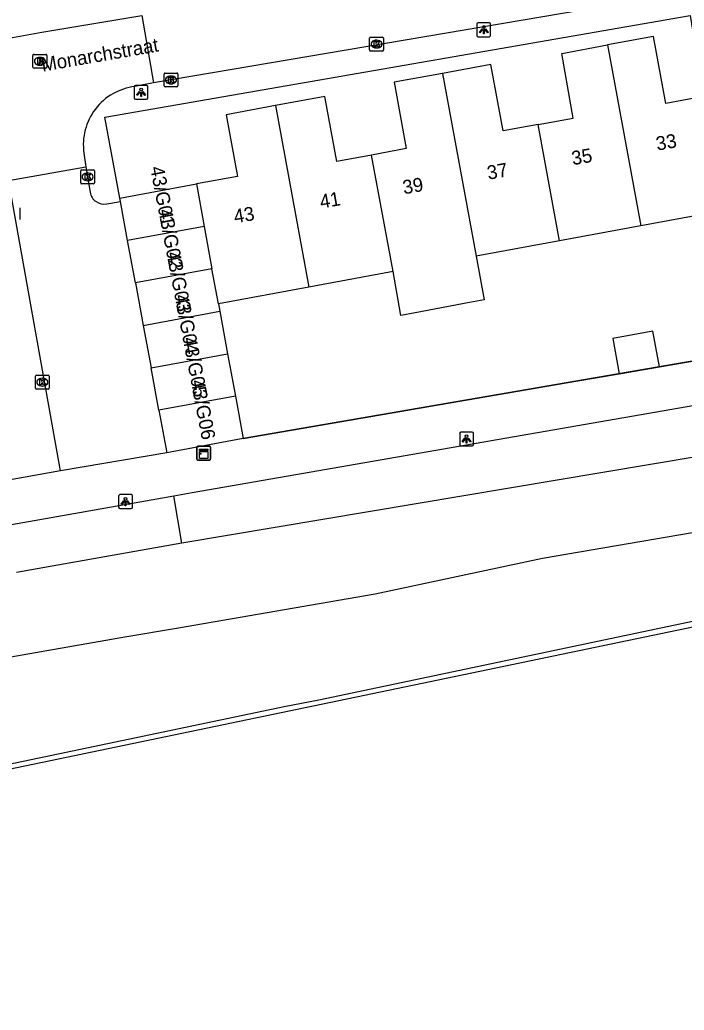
# Model space of a CAD drawing. Extents: x 162880 to 165536, y 384011 to 385179.
# Drawn here: x 164359.8 to 164407.7, y 384233.6 to 384305 of the extents above; entities that cross this region are included whole.
import ezdxf

# ---------------------------------------------------------------- set-up
doc = ezdxf.new("R2010")
doc.units = 0
for name, color, linetype in [('IMGEO_Geluidsscherm', 7, 'Continuous'), ('IMGEO_Groenvoorziening', 7, 'Continuous'), ('IMGEO_Hek', 7, 'Continuous'), ('IMGEO_Kast', 7, 'Continuous'), ('IMGEO_Kolk', 7, 'Continuous'), ('IMGEO_Lichtpunt', 7, 'Continuous'), ('IMGEO_Muur', 7, 'Continuous'), ('IMGEO_Openbare_ruimte_label', 7, 'Continuous'), ('IMGEO_Pand', 7, 'Continuous'), ('IMGEO_Pand_nummerreeks', 7, 'Continuous'), ('IMGEO_Rijbaan_lokaal_open', 7, 'Continuous'), ('IMGEO_Rioolput', 7, 'Continuous'), ('IMGEO_Spoorbaan_halfverhard', 7, 'Continuous'), ('IMGEO_Voetpad_open', 7, 'Continuous')]:
    doc.layers.add(name, color=color, linetype=linetype)

msp = doc.modelspace()

# ---------------------------------------------------------------- linework, layer by layer
at = {"layer": 'IMGEO_Geluidsscherm'}
msp.add_lwpolyline([(164676.85, 384317.503), (164663.933, 384314.802), (164648.266, 384311.595), (164636.969, 384309.223), (164597.183, 384300.976), (164565.574, 384294.368), (164548.747, 384290.97), (164534.634, 384287.879), (164524.441, 384285.774), (164509.439, 384282.631), (164506.722, 384282.083), (164492.433, 384279.293), (164482.587, 384277.14), (164470.079, 384274.477), (164466.147, 384273.624), (164450.636, 384270.401), (164434.466, 384267.046), (164426.586, 384265.503), (164423.587, 384264.967), (164410.248, 384262.029), (164381.356, 384255.946), (164378.846, 384255.471), (164286.152, 384236.059)], dxfattribs=at)
at = {"layer": 'IMGEO_Groenvoorziening'}
for points in [[(164332.753, 384254.442), (164367.352, 384260.503), (164371.077, 384261.125), (164385.399, 384263.612), (164397.49, 384266.196), (164412.669, 384268.778), (164431.26, 384272.662), (164431.272, 384272.664), (164433.193, 384273.044), (164448.321, 384276.269), (164450.983, 384279.512), (164456.803, 384278.493), (164479.257, 384283.495), (164483.175, 384284.701), (164485.578, 384284.269), (164503.501, 384287.513), (164502.968, 384290.256)], [(164408.706, 384273.531), (164371.45, 384267.278)], [(164371.45, 384267.278), (164370.883, 384270.681)], [(164371.45, 384267.278), (164359.532, 384265.161)]]:
    msp.add_lwpolyline(points, dxfattribs=at)
at = {"layer": 'IMGEO_Hek'}
msp.add_lwpolyline([(164444.165, 384268.675), (164308.907, 384240.511), (164298.742, 384238.478), (164283.523, 384235.158)], dxfattribs=at)
at = {"layer": 'IMGEO_Kast'}
for p, q in [((164372.535, 384273.339), (164372.535, 384274.18)), ((164372.535, 384274.18), (164372.535, 384273.339)), ((164372.61, 384274.264), (164373.451, 384274.264)), ((164373.451, 384274.264), (164372.61, 384274.264)), ((164373.535, 384274.189), (164373.535, 384273.348)), ((164373.535, 384273.348), (164373.535, 384274.189)), ((164373.46, 384273.264), (164372.619, 384273.264)), ((164372.619, 384273.264), (164373.46, 384273.264))]:
    msp.add_line(p, q, dxfattribs=at)
for points in [[(164372.73, 384274.054), (164373.33, 384274.054), (164373.33, 384273.969), (164372.73, 384273.969), (164372.73, 384274.054)], [(164372.73, 384273.879), (164373.33, 384273.879), (164373.33, 384273.39), (164372.73, 384273.39), (164372.73, 384273.879)]]:
    msp.add_lwpolyline(points, dxfattribs=at)
msp.add_circle((164372.814, 384273.728), 0.0377, dxfattribs=at)
for centre, start, end in [((164372.613, 384274.186), 92.4484, 184.28452), ((164372.613, 384274.186), 92.4484, 184.28452), ((164373.457, 384274.186), 2.4484, 94.28452), ((164373.457, 384274.186), 2.4484, 94.28452), ((164372.613, 384273.342), 182.4484, 274.28452), ((164372.613, 384273.342), 182.4484, 274.28452), ((164373.457, 384273.342), 272.4484, 4.28452), ((164373.457, 384273.342), 272.4484, 4.28452)]:
    msp.add_arc(centre, 0.0779, start, end, dxfattribs=at)
at = {"layer": 'IMGEO_Kolk'}
for p, q in [((164385.012, 384302.86), (164385.012, 384303.712)), ((164385.087, 384303.786), (164385.939, 384303.786)), ((164385.5, 384303.566), (164385.525, 384303.566)), ((164386.013, 384303.712), (164386.013, 384302.86)), ((164385.939, 384302.786), (164385.087, 384302.786)), ((164385.523, 384303.006), (164385.498, 384303.006)), ((164370.175, 384300.272), (164370.175, 384301.124)), ((164370.25, 384301.198), (164371.102, 384301.198)), ((164370.663, 384300.978), (164370.688, 384300.978)), ((164371.176, 384301.124), (164371.176, 384300.272)), ((164371.102, 384300.198), (164370.25, 384300.198)), ((164370.686, 384300.418), (164370.661, 384300.418)), ((164364.16, 384293.283), (164364.16, 384294.135)), ((164364.235, 384294.209), (164365.087, 384294.209)), ((164365.161, 384294.135), (164365.161, 384293.283)), ((164364.671, 384293.429), (164364.646, 384293.429)), ((164364.648, 384293.989), (164364.673, 384293.989)), ((164365.087, 384293.209), (164364.235, 384293.209)), ((164359.768, 384291.469), (164359.768, 384290.617)), ((164360.895, 384278.465), (164360.895, 384279.317)), ((164360.97, 384279.391), (164361.822, 384279.391)), ((164361.383, 384279.171), (164361.408, 384279.171)), ((164361.896, 384279.317), (164361.896, 384278.465)), ((164361.822, 384278.391), (164360.97, 384278.391)), ((164361.406, 384278.611), (164361.381, 384278.611))]:
    msp.add_line(p, q, dxfattribs=at)
for points in [[(164385.012, 384302.86), (164385.012, 384303.712)], [(164385.087, 384303.786), (164385.939, 384303.786)], [(164385.333, 384303.486), (164385.456, 384303.486), (164385.456, 384303.335), (164385.586, 384303.486), (164385.75, 384303.486), (164385.604, 384303.335), (164385.757, 384303.086), (164385.605, 384303.086), (164385.52, 384303.25), (164385.456, 384303.183), (164385.456, 384303.086), (164385.333, 384303.086), (164385.333, 384303.486)], [(164386.013, 384303.712), (164386.013, 384302.86)], [(164385.939, 384302.786), (164385.087, 384302.786)], [(164370.175, 384300.272), (164370.175, 384301.124)], [(164370.25, 384301.198), (164371.102, 384301.198)], [(164370.496, 384300.898), (164370.619, 384300.898), (164370.619, 384300.747), (164370.749, 384300.898), (164370.913, 384300.898), (164370.767, 384300.747), (164370.92, 384300.498), (164370.768, 384300.498), (164370.683, 384300.662), (164370.619, 384300.595), (164370.619, 384300.498), (164370.496, 384300.498), (164370.496, 384300.898)], [(164371.176, 384301.124), (164371.176, 384300.272)], [(164371.102, 384300.198), (164370.25, 384300.198)], [(164364.16, 384293.283), (164364.16, 384294.135)], [(164364.235, 384294.209), (164365.087, 384294.209)], [(164365.161, 384294.135), (164365.161, 384293.283)], [(164364.481, 384293.909), (164364.604, 384293.909), (164364.604, 384293.758), (164364.734, 384293.909), (164364.898, 384293.909), (164364.752, 384293.758), (164364.905, 384293.509), (164364.753, 384293.509), (164364.668, 384293.673), (164364.604, 384293.606), (164364.604, 384293.509), (164364.481, 384293.509), (164364.481, 384293.909)], [(164365.087, 384293.209), (164364.235, 384293.209)], [(164359.768, 384291.469), (164359.768, 384290.617)], [(164360.895, 384278.465), (164360.895, 384279.317)], [(164360.97, 384279.391), (164361.822, 384279.391)], [(164361.216, 384279.091), (164361.339, 384279.091), (164361.339, 384278.94), (164361.469, 384279.091), (164361.633, 384279.091), (164361.487, 384278.94), (164361.64, 384278.691), (164361.488, 384278.691), (164361.403, 384278.855), (164361.339, 384278.788), (164361.339, 384278.691), (164361.216, 384278.691), (164361.216, 384279.091)], [(164361.896, 384279.317), (164361.896, 384278.465)], [(164361.822, 384278.391), (164360.97, 384278.391)]]:
    msp.add_lwpolyline(points, dxfattribs=at)
for centre, start, end in [((164385.089, 384303.71), 91.55205, 178.44795), ((164385.089, 384303.71), 91.55205, 178.44795), ((164385.937, 384303.71), 1.55205, 88.44795), ((164385.937, 384303.71), 1.55205, 88.44795), ((164385.089, 384302.862), 181.55205, 268.44795), ((164385.089, 384302.862), 181.55205, 268.44795), ((164385.937, 384302.862), 271.55205, 358.44795), ((164385.937, 384302.862), 271.55205, 358.44795), ((164370.252, 384301.122), 91.55205, 178.44795), ((164370.252, 384301.122), 91.55205, 178.44795), ((164371.1, 384301.122), 1.55205, 88.44795), ((164371.1, 384301.122), 1.55205, 88.44795), ((164370.252, 384300.274), 181.55205, 268.44795), ((164370.252, 384300.274), 181.55205, 268.44795), ((164371.1, 384300.274), 271.55205, 358.44795), ((164371.1, 384300.274), 271.55205, 358.44795), ((164364.237, 384294.133), 91.55205, 178.44795), ((164364.237, 384294.133), 91.55205, 178.44795), ((164365.085, 384294.133), 1.55205, 88.44795), ((164365.085, 384294.133), 1.55205, 88.44795), ((164364.237, 384293.285), 181.55205, 268.44795), ((164364.237, 384293.285), 181.55205, 268.44795), ((164365.085, 384293.285), 271.55205, 358.44795), ((164365.085, 384293.285), 271.55205, 358.44795), ((164360.972, 384279.315), 91.55205, 178.44795), ((164360.972, 384279.315), 91.55205, 178.44795), ((164361.82, 384279.315), 1.55205, 88.44795), ((164361.82, 384279.315), 1.55205, 88.44795), ((164360.972, 384278.467), 181.55205, 268.44795), ((164360.972, 384278.467), 181.55205, 268.44795), ((164361.82, 384278.467), 271.55205, 358.44795), ((164361.82, 384278.467), 271.55205, 358.44795)]:
    msp.add_arc(centre, 0.0765, start, end, dxfattribs=at)
for centre, major_axis, ratio, start_param, end_param in [((164385.499, 384303.286), (-0.387, 0.002), 0.722429, 4.712389, 7.853982), ((164385.524, 384303.286), (-0.39, 0.002), 0.717154, 1.570796, 4.712389), ((164370.662, 384300.698), (-0.387, 0.002), 0.722429, 4.712389, 7.853982), ((164370.687, 384300.698), (-0.39, 0.002), 0.717154, 1.570796, 4.712389), ((164364.647, 384293.709), (-0.387, 0.002), 0.722429, 4.712389, 7.853982), ((164364.672, 384293.709), (-0.39, 0.002), 0.717154, 1.570796, 4.712389), ((164361.382, 384278.891), (-0.387, 0.002), 0.722429, 4.712389, 7.853982), ((164361.407, 384278.891), (-0.39, 0.002), 0.717154, 1.570796, 4.712389)]:
    msp.add_ellipse(centre, major_axis=major_axis, ratio=ratio, start_param=start_param, end_param=end_param, dxfattribs=at)
at = {"layer": 'IMGEO_Lichtpunt'}
for p, q in [((164393.649, 384304.816), (164392.841, 384304.816)), ((164393.649, 384304.816), (164392.841, 384304.816)), ((164392.747, 384304.721), (164392.747, 384303.914)), ((164392.747, 384304.721), (164392.747, 384303.914)), ((164393.743, 384303.914), (164393.743, 384304.721)), ((164393.743, 384303.914), (164393.743, 384304.721)), ((164392.841, 384303.82), (164393.649, 384303.82)), ((164392.841, 384303.82), (164393.649, 384303.82)), ((164368.019, 384300.211), (164368.019, 384299.404)), ((164368.019, 384300.211), (164368.019, 384299.404)), ((164368.921, 384300.306), (164368.113, 384300.306)), ((164368.921, 384300.306), (164368.113, 384300.306)), ((164369.015, 384299.404), (164369.015, 384300.211)), ((164369.015, 384299.404), (164369.015, 384300.211)), ((164368.113, 384299.31), (164368.921, 384299.31)), ((164368.113, 384299.31), (164368.921, 384299.31)), ((164391.507, 384275.196), (164391.507, 384274.389)), ((164391.507, 384275.196), (164391.507, 384274.389)), ((164392.409, 384275.291), (164391.601, 384275.291)), ((164392.409, 384275.291), (164391.601, 384275.291)), ((164392.503, 384274.389), (164392.503, 384275.196)), ((164392.503, 384274.389), (164392.503, 384275.196)), ((164391.601, 384274.295), (164392.409, 384274.295)), ((164391.601, 384274.295), (164392.409, 384274.295)), ((164366.901, 384270.679), (164366.901, 384269.872)), ((164366.901, 384270.679), (164366.901, 384269.872)), ((164367.803, 384270.774), (164366.995, 384270.774)), ((164367.803, 384270.774), (164366.995, 384270.774)), ((164367.897, 384269.872), (164367.897, 384270.679)), ((164367.897, 384269.872), (164367.897, 384270.679)), ((164366.995, 384269.778), (164367.803, 384269.778)), ((164366.995, 384269.778), (164367.803, 384269.778))]:
    msp.add_line(p, q, dxfattribs=at)
for points in [[(164393.121, 384304.385), (164393.16, 384304.357), (164392.972, 384304.095), (164392.934, 384304.122), (164393.121, 384304.385)], [(164393.223, 384304.337), (164393.27, 384304.337), (164393.27, 384304.015), (164393.223, 384304.015), (164393.223, 384304.337)], [(164393.333, 384304.357), (164393.371, 384304.384), (164393.558, 384304.122), (164393.519, 384304.094), (164393.333, 384304.357)], [(164368.393, 384299.875), (164368.432, 384299.847), (164368.244, 384299.585), (164368.206, 384299.612), (164368.393, 384299.875)], [(164368.495, 384299.827), (164368.542, 384299.827), (164368.542, 384299.505), (164368.495, 384299.505), (164368.495, 384299.827)], [(164368.605, 384299.847), (164368.643, 384299.874), (164368.83, 384299.612), (164368.791, 384299.584), (164368.605, 384299.847)], [(164391.881, 384274.86), (164391.92, 384274.832), (164391.732, 384274.57), (164391.694, 384274.597), (164391.881, 384274.86)], [(164391.983, 384274.812), (164392.03, 384274.812), (164392.03, 384274.49), (164391.983, 384274.49), (164391.983, 384274.812)], [(164392.093, 384274.832), (164392.131, 384274.859), (164392.318, 384274.597), (164392.279, 384274.569), (164392.093, 384274.832)], [(164367.275, 384270.343), (164367.314, 384270.315), (164367.126, 384270.053), (164367.088, 384270.08), (164367.275, 384270.343)], [(164367.377, 384270.295), (164367.424, 384270.295), (164367.424, 384269.973), (164367.377, 384269.973), (164367.377, 384270.295)], [(164367.487, 384270.315), (164367.525, 384270.342), (164367.712, 384270.08), (164367.673, 384270.052), (164367.487, 384270.315)]]:
    msp.add_lwpolyline(points, dxfattribs=at)
for centre in [(164393.246, 384304.519), (164368.518, 384300.009), (164392.006, 384274.994), (164367.4, 384270.477)]:
    msp.add_circle(centre, 0.0994, dxfattribs=at)
for centre, start, end in [((164392.841, 384304.721), 90, 180), ((164392.841, 384304.721), 90, 180), ((164393.649, 384304.721), 0, 90), ((164393.649, 384304.721), 0, 90), ((164392.841, 384303.914), 180, 270), ((164392.841, 384303.914), 180, 270), ((164393.649, 384303.914), 270, 0), ((164393.649, 384303.914), 270, 360), ((164368.113, 384300.211), 90, 180), ((164368.113, 384300.211), 90, 180), ((164368.921, 384300.211), 0, 90), ((164368.921, 384300.211), 0, 90), ((164368.113, 384299.404), 180, 270), ((164368.113, 384299.404), 180, 270), ((164368.921, 384299.404), 270, 0), ((164368.921, 384299.404), 270, 360), ((164391.601, 384275.196), 90, 180), ((164391.601, 384275.196), 90, 180), ((164392.409, 384275.196), 0, 90), ((164392.409, 384275.196), 0, 90), ((164391.601, 384274.389), 180, 270), ((164391.601, 384274.389), 180, 270), ((164392.409, 384274.389), 270, 0), ((164392.409, 384274.389), 270, 360), ((164366.995, 384270.679), 90, 180), ((164366.995, 384270.679), 90, 180), ((164367.803, 384270.679), 0, 90), ((164367.803, 384270.679), 0, 90), ((164366.995, 384269.872), 180, 270), ((164366.995, 384269.872), 180, 270), ((164367.803, 384269.872), 270, 0), ((164367.803, 384269.872), 270, 360)]:
    msp.add_arc(centre, 0.0946, start, end, dxfattribs=at)
at = {"layer": 'IMGEO_Muur'}
for points in [[(164412.318, 384281.098), (164399.901, 384278.956)], [(164399.901, 384278.956), (164375.896, 384274.815)]]:
    msp.add_lwpolyline(points, dxfattribs=at)
at = {"layer": 'IMGEO_Pand'}
for points in [[(164409.066, 384299.492), (164406.382, 384298.997), (164405.491, 384303.832), (164402.18, 384303.222)], [(164397.17, 384297.485), (164399.698, 384297.951), (164398.87, 384302.612), (164402.18, 384303.222)], [(164402.18, 384303.222), (164404.586, 384290.17)], [(164397.17, 384297.485), (164394.641, 384297.019), (164393.757, 384301.814), (164390.265, 384301.17)], [(164390.265, 384301.17), (164386.774, 384300.527), (164387.656, 384295.743), (164385.148, 384295.281)], [(164390.265, 384301.17), (164392.697, 384287.978)], [(164385.148, 384295.281), (164382.639, 384294.818), (164381.776, 384299.5), (164378.212, 384298.843)], [(164378.212, 384298.843), (164374.652, 384298.186), (164375.472, 384293.738), (164372.506, 384293.191)], [(164378.212, 384298.843), (164380.625, 384285.753)], [(164398.718, 384289.088), (164397.17, 384297.485)], [(164386.698, 384286.872), (164385.148, 384295.281)], [(164366.979, 384292.173), (164372.506, 384293.191)], [(164372.506, 384293.191), (164373.071, 384290.129)], [(164367.024, 384291.93), (164366.979, 384292.173)], [(164367.544, 384289.11), (164367.073, 384291.661), (164367.024, 384291.93)], [(164410.581, 384291.275), (164404.586, 384290.17)], [(164373.071, 384290.129), (164367.544, 384289.11)], [(164373.071, 384290.129), (164373.636, 384287.067)], [(164404.586, 384290.17), (164398.718, 384289.088)], [(164368.108, 384286.047), (164367.544, 384289.11)], [(164398.718, 384289.088), (164392.697, 384287.978)], [(164392.697, 384287.978), (164393.279, 384284.821), (164392.227, 384284.627), (164388.298, 384283.903), (164387.256, 384283.711), (164386.698, 384286.872)], [(164373.636, 384287.067), (164368.108, 384286.047)], [(164374.101, 384284.55), (164373.636, 384287.067)], [(164386.698, 384286.872), (164380.625, 384285.753)], [(164368.108, 384286.047), (164368.673, 384282.984)], [(164380.625, 384285.753), (164374.101, 384284.55)], [(164374.101, 384284.55), (164374.202, 384284.004)], [(164368.673, 384282.984), (164374.202, 384284.004)], [(164374.202, 384284.004), (164374.766, 384280.941)], [(164368.673, 384282.984), (164369.238, 384279.922)], [(164405.931, 384279.996), (164405.457, 384282.566), (164402.551, 384282.031), (164403.019, 384279.494)], [(164369.238, 384279.922), (164374.766, 384280.941)], [(164374.766, 384280.941), (164375.331, 384277.878)], [(164369.802, 384276.859), (164369.238, 384279.922)], [(164403.019, 384279.494), (164405.931, 384279.996)], [(164375.331, 384277.878), (164369.802, 384276.859)], [(164375.331, 384277.878), (164375.896, 384274.815)], [(164369.802, 384276.859), (164370.367, 384273.796)], [(164375.896, 384274.815), (164370.367, 384273.796)]]:
    msp.add_lwpolyline(points, dxfattribs=at)
at = {"layer": 'IMGEO_Rijbaan_lokaal_open'}
for points in [[(164403.033, 384306.195), (164369.425, 384300.48)], [(164351.798, 384302.425), (164361.356, 384304.138), (164368.583, 384305.341)], [(164368.583, 384305.341), (164369.425, 384300.48)], [(164369.425, 384300.48), (164368.07, 384300.23)], [(164364.391, 384295.424), (164364.535, 384294.432)], [(164358.943, 384293.437), (164364.535, 384294.432)], [(164364.535, 384294.432), (164364.856, 384292.588)], [(164362.71, 384272.494), (164359.019, 384293.076)], [(164366.037, 384291.76), (164367.024, 384291.93)], [(164370.367, 384273.796), (164362.71, 384272.494)]]:
    msp.add_lwpolyline(points, dxfattribs=at)
for centre, radius, start, end in [((164368.589, 384296.021), 4.24, 97.03205, 188.09973), ((164365.833, 384292.725), 0.986, 187.97833, 281.95301)]:
    msp.add_arc(centre, radius, start, end, dxfattribs=at)
at = {"layer": 'IMGEO_Rioolput'}
for p, q in [((164360.719, 384301.618), (164360.719, 384302.47)), ((164360.794, 384302.544), (164361.646, 384302.544)), ((164361.207, 384302.324), (164361.232, 384302.324)), ((164361.72, 384302.47), (164361.72, 384301.618)), ((164361.646, 384301.544), (164360.794, 384301.544)), ((164361.23, 384301.764), (164361.205, 384301.764))]:
    msp.add_line(p, q, dxfattribs=at)
for points in [[(164360.719, 384301.618), (164360.719, 384302.47)], [(164360.794, 384302.544), (164361.646, 384302.544)], [(164361.308, 384302.242), (164361.056, 384302.244), (164361.056, 384301.844)], [(164361.056, 384301.844), (164361.18, 384301.844), (164361.18, 384302.006), (164361.191, 384302.006)], [(164361.234, 384302.163), (164361.18, 384302.163), (164361.18, 384302.082)], [(164361.18, 384302.082), (164361.232, 384302.082)], [(164361.238, 384301.977), (164361.309, 384301.844), (164361.449, 384301.844), (164361.384, 384301.97)], [(164361.72, 384302.47), (164361.72, 384301.618)], [(164361.646, 384301.544), (164360.794, 384301.544)]]:
    msp.add_lwpolyline(points, dxfattribs=at)
for centre, radius, start, end in [((164360.796, 384302.468), 0.0765, 91.55205, 178.44795), ((164360.796, 384302.468), 0.0765, 91.55205, 178.44795), ((164361.19, 384301.953), 0.0533, 26.02933, 88.69889), ((164361.216, 384302.271), 0.19, 274.7715, 282.96867), ((164361.24, 384302.067), 0.0964, 77.00612, 93.18647), ((164361.254, 384302.124), 0.0378, 276.66336, 79.67722), ((164361.307, 384302.132), 0.109, 350.36119, 89.41601), ((164361.305, 384302.132), 0.112, 277.58423, 350.98172), ((164361.289, 384301.917), 0.108, 29.51342, 73.79051), ((164361.644, 384302.468), 0.0765, 1.55205, 88.44795), ((164361.644, 384302.468), 0.0765, 1.55205, 88.44795), ((164360.796, 384301.62), 0.0765, 181.55205, 268.44795), ((164360.796, 384301.62), 0.0765, 181.55205, 268.44795), ((164361.644, 384301.62), 0.0765, 271.55205, 358.44795), ((164361.644, 384301.62), 0.0765, 271.55205, 358.44795)]:
    msp.add_arc(centre, radius, start, end, dxfattribs=at)
for centre, major_axis, ratio, start_param, end_param in [((164361.206, 384302.044), (-0.387, 0.002), 0.722429, 4.712389, 7.853982), ((164361.231, 384302.044), (-0.39, 0.002), 0.717154, 1.570796, 4.712389)]:
    msp.add_ellipse(centre, major_axis=major_axis, ratio=ratio, start_param=start_param, end_param=end_param, dxfattribs=at)
at = {"layer": 'IMGEO_Spoorbaan_halfverhard'}
msp.add_lwpolyline([(164676.805, 384317.608), (164676.845, 384317.39), (164570.841, 384295.099), (164487.306, 384277.828), (164444.165, 384268.675), (164308.907, 384240.511), (164298.742, 384238.478), (164285.806, 384235.656), (164283.523, 384235.158), (164279.904, 384234.412), (164276.237, 384233.569)], dxfattribs=at)
at = {"layer": 'IMGEO_Voetpad_open'}
for points in [[(164366.979, 384292.173), (164365.905, 384298.004), (164408.129, 384305.35), (164409.066, 384299.492)], [(164405.931, 384279.996), (164412.318, 384281.098)], [(164375.896, 384274.815), (164399.901, 384278.956), (164403.019, 384279.494)], [(164370.883, 384270.681), (164372.217, 384270.915), (164409.581, 384277.423), (164413.067, 384278.013), (164413.347, 384276.23)], [(164362.71, 384272.494), (164358.244, 384271.696)], [(164357.5, 384268.334), (164357.909, 384268.406), (164370.883, 384270.681)]]:
    msp.add_lwpolyline(points, dxfattribs=at)

# ---------------------------------------------------------------- texts
at = {"layer": 'IMGEO_Openbare_ruimte_label'}
msp.add_text('Monarchstraat', height=1, rotation=9.90508, dxfattribs=at).set_placement((164361.413, 384301.293))
at = {"layer": 'IMGEO_Pand_nummerreeks'}
for s, rotation, p in [('33', 9.77798, (164405.762, 384295.594)), ('35', 9.77798, (164399.669, 384294.544)), ('43/G01', 280.76703, (164369.173, 384294.378)), ('37', 9.77798, (164393.575, 384293.494)), ('39', 9.77798, (164387.482, 384292.444)), ('41', 9.77798, (164381.501, 384291.413)), ('43/G02', 280.76703, (164369.759, 384291.297)), ('43', 9.77798, (164375.296, 384290.344)), ('43/G03', 280.76703, (164370.345, 384288.216)), ('43/G04', 280.76703, (164370.931, 384285.135)), ('43/G05', 280.76703, (164371.517, 384282.054)), ('43/G06', 280.76703, (164372.103, 384278.974))]:
    msp.add_text(s, height=1, rotation=rotation, dxfattribs=at).set_placement(p)

doc.saveas('drawing.dxf')
